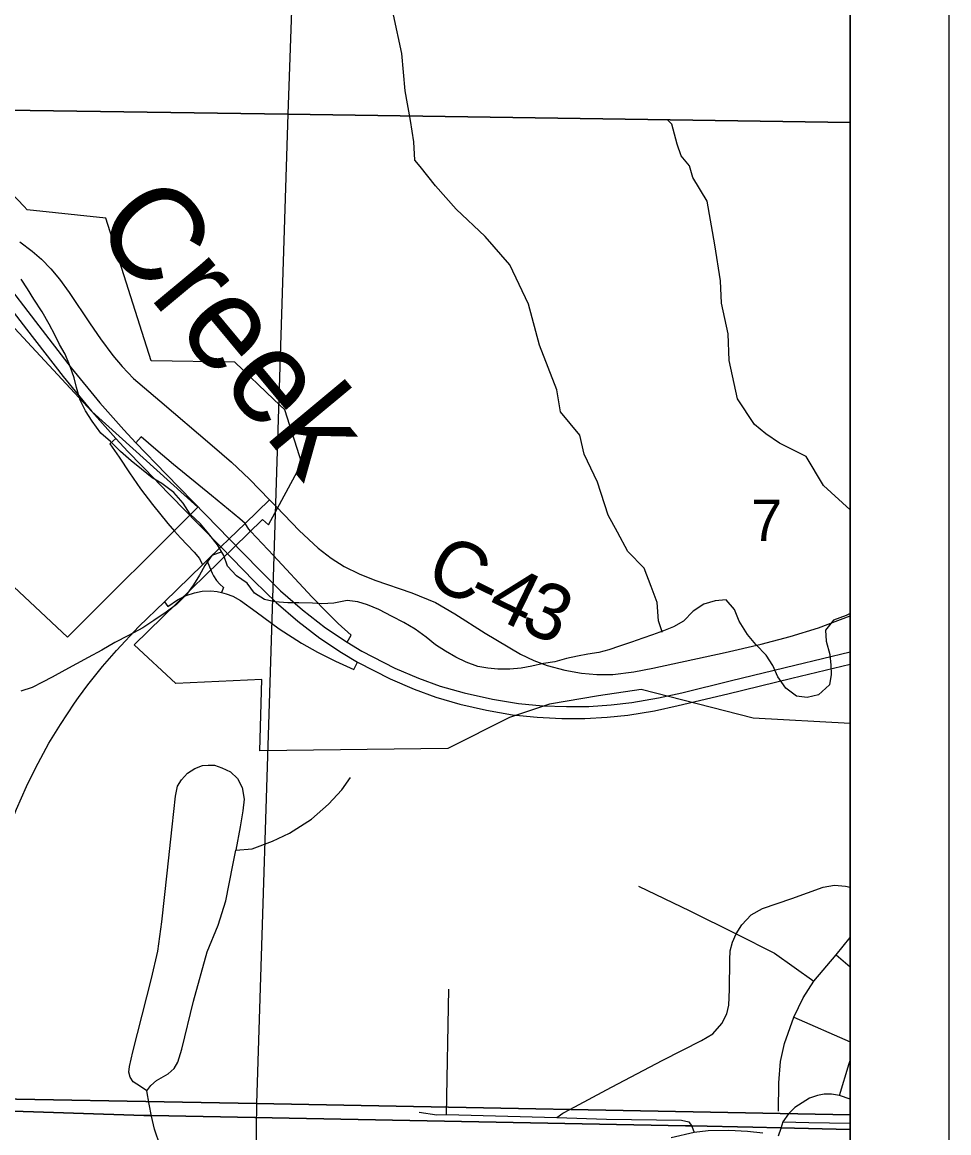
# Model space of a CAD drawing. Extents: x -19 to 40.8, y -1.8 to 26.1.
# Drawn here: x 8.061 to 9, y 15.876 to 17.001 of the extents above; entities that cross this region are included whole.
import ezdxf

# ---------------------------------------------------------------- set-up
doc = ezdxf.new("R2010")
doc.units = 0
for name, color, linetype in [('Default', 7, 'Continuous'), ('GM_X_Corporation', 7, 'Continuous'), ('GM_X_County_Road', 7, 'Continuous'), ('GM_X_County_Road_Text', 7, 'Continuous'), ('GM_X_Minor_River', 7, 'Continuous'), ('GM_X_Rail_Line', 7, 'Continuous'), ('GM_X_Rail_Line_Text', 7, 'Continuous'), ('GM_X_Section', 7, 'Continuous'), ('GM_X_Section_Text', 7, 'Continuous'), ('GM_X_State_Route', 7, 'Continuous'), ('GM_X_Township_Road', 7, 'Continuous'), ('RW_P_Text', 7, 'Continuous'), ('SH_Data', 7, 'Continuous')]:
    doc.layers.add(name, color=color, linetype=linetype)

msp = doc.modelspace()

# ---------------------------------------------------------------- linework, layer by layer
at = {"layer": 'Default'}
for p, q in [((8.0628, 16.814), (7.9759, 16.9049)), ((8.066, 16.8106), (8.0628, 16.814)), ((8.1458, 16.8022), (8.066, 16.8106)), ((8.1918, 16.6576), (8.1458, 16.8022)), ((8.0335, 16.7116), (8.1315, 16.6064)), ((8.2766, 16.6563), (8.1918, 16.6576)), ((8.3159, 16.6186), (8.2766, 16.6563)), ((8.327, 16.608), (8.3159, 16.6186)), ((8.1315, 16.6064), (8.2389, 16.5095)), ((8.3442, 16.5541), (8.327, 16.608)), ((8.3105, 16.4915), (8.3442, 16.5541)), ((8.2389, 16.5095), (8.107, 16.3778)), ((8.1743, 16.3699), (8.3044, 16.4969)), ((8.3044, 16.4969), (8.3105, 16.4915)), ((8.107, 16.3778), (8.0306, 16.4492)), ((8.2166, 16.3309), (8.1743, 16.3699)), ((8.3038, 16.335), (8.2166, 16.3309)), ((8.3017, 16.2626), (8.3038, 16.335)), ((8.6883, 16.3249), (8.645, 16.3183)), ((8.8018, 16.2956), (8.6883, 16.3249)), ((8.645, 16.3183), (8.5953, 16.3098)), ((8.5953, 16.3098), (8.5548, 16.2965)), ((8.5548, 16.2965), (8.4924, 16.2651)), ((8.9, 16.2904), (8.8018, 16.2956)), ((8.9, 14.2909), (8.9, 16.2904)), ((8.4924, 16.2651), (8.3017, 16.2626))]:
    msp.add_line(p, q, dxfattribs=at)
for points in [[(8.9, 16.8989), (8.9, 17.9188), (8.3666, 17.9389), (8.3301, 16.9076)], [(8.9, 15.8939), (8.9, 16.8989), (8.3301, 16.9076), (8.2983, 15.9055)], [(8.9, 14.8168), (8.9, 15.8939), (8.2983, 15.9055), (8.2842, 14.8321)]]:
    msp.add_lwpolyline(points, close=True, dxfattribs=at)
at = {"layer": 'GM_X_Corporation'}
for p, q in [((8.2868, 16.4928), (8.3116, 16.5169)), ((8.3116, 16.5169), (8.3186, 16.5097))]:
    msp.add_line(p, q, dxfattribs=at)
for points in [[(8.0586, 16.7781), (8.071, 16.7688), (8.0806, 16.7605), (8.0899, 16.7507), (8.0987, 16.7403), (8.1086, 16.7268), (8.13, 16.6951), (8.1403, 16.6798), (8.1528, 16.6632), (8.1623, 16.6518), (8.1739, 16.6399), (8.2004, 16.617), (8.2535, 16.5719), (8.2729, 16.555), (8.2913, 16.5377), (8.3116, 16.5169)], [(8.3186, 16.5097), (8.3418, 16.4858), (8.3609, 16.4678), (8.3741, 16.4578), (8.3873, 16.4493), (8.4023, 16.4419), (8.4183, 16.4355), (8.4557, 16.4228), (8.4799, 16.4127), (8.4993, 16.4013), (8.53, 16.3819), (8.5658, 16.3606), (8.5796, 16.3542), (8.5931, 16.3489), (8.6108, 16.3442), (8.6279, 16.3412), (8.6432, 16.3401), (8.6595, 16.3399), (8.6809, 16.3427), (8.7, 16.3465), (8.7732, 16.3623), (8.81, 16.3706), (8.8392, 16.3784), (8.8681, 16.3873), (8.9, 16.3995)], [(8.1181, 16.3165), (8.1276, 16.3294), (8.1422, 16.3479), (8.1564, 16.3644), (8.1793, 16.3885), (8.2051, 16.4136), (8.2436, 16.451), (8.248, 16.4553), (8.2622, 16.4691), (8.2707, 16.4773), (8.2868, 16.4928)], [(8.0146, 15.935), (8.0134, 15.9471), (8.0121, 15.9781), (8.0125, 16.0094), (8.0143, 16.0368), (8.0178, 16.0672), (8.0207, 16.0859), (8.0249, 16.1068), (8.0298, 16.1277), (8.0351, 16.1467), (8.0412, 16.1656), (8.0476, 16.1845), (8.0551, 16.2034), (8.0653, 16.2266), (8.0744, 16.2452), (8.0881, 16.2703), (8.0996, 16.2893), (8.114, 16.3108), (8.1181, 16.3165)], [(8.9, 15.9098), (8.8891, 15.9134), (8.8812, 15.9147), (8.8738, 15.9149), (8.8668, 15.9136), (8.8587, 15.9109), (8.8438, 15.9014), (8.8432, 15.9007)], [(8.8432, 15.9007), (8.8375, 15.895), (8.8319, 15.8868), (8.8298, 15.8801), (8.8272, 15.8722)]]:
    msp.add_lwpolyline(points, dxfattribs=at)
at = {"layer": 'GM_X_County_Road'}
for points in [[(8.2868, 16.4928), (8.2815, 16.4977), (8.2527, 16.5214), (8.2144, 16.5527), (8.1963, 16.5678), (8.1816, 16.5807), (8.1761, 16.5747)], [(8.1559, 16.5789), (8.1497, 16.5735), (8.1591, 16.56), (8.1696, 16.5443), (8.1809, 16.528), (8.1929, 16.512), (8.2085, 16.4928), (8.2154, 16.4852)], [(8.2927, 16.4848), (8.2905, 16.4872), (8.2868, 16.4928)], [(8.2154, 16.4852), (8.2215, 16.4785), (8.2353, 16.464), (8.2407, 16.4573), (8.2436, 16.451)], [(8.3904, 16.3726), (8.3944, 16.3799), (8.3811, 16.3915), (8.3703, 16.4023), (8.3546, 16.4187), (8.3157, 16.4604), (8.2927, 16.4848)], [(8.248, 16.4553), (8.2501, 16.4507), (8.2525, 16.4449)], [(8.2525, 16.4449), (8.2534, 16.4426), (8.2549, 16.4398), (8.2577, 16.4353), (8.2613, 16.4313), (8.2649, 16.428), (8.2628, 16.423)], [(8.2251, 16.4189), (8.227, 16.4198), (8.2354, 16.4227), (8.2432, 16.4242), (8.252, 16.4246), (8.2584, 16.424), (8.2628, 16.423), (8.2677, 16.4216), (8.2743, 16.4192), (8.2822, 16.4149), (8.2979, 16.4033), (8.3215, 16.3861), (8.3439, 16.3717), (8.3602, 16.3626), (8.3786, 16.3533), (8.3972, 16.3451), (8.4007, 16.3525)], [(8.2051, 16.4136), (8.2086, 16.4089), (8.2184, 16.4156), (8.2251, 16.4189)]]:
    msp.add_lwpolyline(points, dxfattribs=at)
at = {"layer": 'GM_X_Rail_Line'}
msp.add_lwpolyline([(8.8116, 15.8752), (8.7961, 15.877), (8.777, 15.8782), (8.7562, 15.8778), (8.7419, 15.8761), (8.7186, 15.8706)], dxfattribs=at)
at = {"layer": 'GM_X_Rail_Line_Text'}
for p, q in [((8.8859, 16.056), (8.9, 16.0438)), ((8.4911, 15.8944), (8.4932, 16.0213)), ((8.8431, 15.9928), (8.9, 15.9679))]:
    msp.add_line(p, q, dxfattribs=at)
for points in [[(8.1872, 15.9181), (8.1808, 15.9226), (8.1734, 15.9272), (8.1704, 15.9321), (8.169, 15.9371), (8.1696, 15.9428), (8.173, 15.9579), (8.1921, 16.0321), (8.1984, 16.0597), (8.2025, 16.0894), (8.2078, 16.1386), (8.2129, 16.1856), (8.2164, 16.2166), (8.2185, 16.2268), (8.2224, 16.2334), (8.2286, 16.2399), (8.2359, 16.2446), (8.2437, 16.2476), (8.2493, 16.2482), (8.2557, 16.248), (8.2634, 16.2455), (8.2722, 16.2413), (8.2793, 16.2347), (8.2838, 16.2256), (8.2859, 16.2136), (8.2847, 16.2017), (8.2819, 16.1856), (8.2774, 16.1621)], [(8.1872, 15.9181), (8.1912, 15.9237), (8.197, 15.9286), (8.2089, 15.9353), (8.2148, 15.9407), (8.2187, 15.9472), (8.2226, 15.9603), (8.2347, 16.0092), (8.2485, 16.0591), (8.2597, 16.0862), (8.2674, 16.1108), (8.2743, 16.1469), (8.2774, 16.1621), (8.2939, 16.1635), (8.3147, 16.1712), (8.3318, 16.1791), (8.3543, 16.1934), (8.3712, 16.2085), (8.385, 16.2231), (8.3938, 16.2355)], [(8.6027, 15.8913), (8.6088, 15.8955), (8.616, 15.8995), (8.6583, 15.9219), (8.7103, 15.9494), (8.7493, 15.9692), (8.7608, 15.9761), (8.77, 15.9863), (8.7752, 15.9964), (8.777, 16.0049), (8.7776, 16.0208), (8.7781, 16.051), (8.7785, 16.0601), (8.7807, 16.0687), (8.7845, 16.0774), (8.7903, 16.0865), (8.7996, 16.0964), (8.8112, 16.1029), (8.8408, 16.1132), (8.8728, 16.1246), (8.8842, 16.1265), (8.8954, 16.1256), (8.9, 16.1246)], [(8.6856, 16.1255), (8.7374, 16.1004), (8.7845, 16.0774), (8.8235, 16.0577), (8.8631, 16.0292)], [(8.8274, 15.8975), (8.8279, 15.9264), (8.8295, 15.948), (8.8335, 15.9662), (8.8431, 15.9928), (8.8524, 16.0124), (8.8631, 16.0292), (8.8859, 16.056), (8.9, 16.0737)], [(8.8891, 15.9134), (8.899, 15.9459), (8.9, 15.9489)], [(8.3504, 15.7054), (8.3429, 15.7215), (8.3351, 15.7346), (8.3259, 15.7469), (8.3131, 15.7589), (8.3012, 15.7689), (8.2884, 15.78), (8.262, 15.8029), (8.2354, 15.8263), (8.2097, 15.8491), (8.2007, 15.8627), (8.1951, 15.8793), (8.1921, 15.8926), (8.1895, 15.9046), (8.1872, 15.9181)], [(8.4632, 15.8965), (8.4812, 15.8939), (8.4911, 15.8944), (8.6027, 15.8913), (8.6532, 15.8895), (8.7291, 15.8884), (8.7364, 15.887), (8.7397, 15.8825), (8.7419, 15.8761)], [(8.8319, 15.8868), (8.8581, 15.8861), (8.9, 15.8856)]]:
    msp.add_lwpolyline(points, dxfattribs=at)
at = {"layer": 'GM_X_Section'}
for points in [[(8.709, 16.3834), (8.7094, 16.3832), (8.7059, 16.3942), (8.7044, 16.4128), (8.6984, 16.429), (8.6913, 16.4475), (8.6747, 16.4644), (8.6642, 16.484), (8.6548, 16.5013), (8.644, 16.5346), (8.6306, 16.5632), (8.6261, 16.5825), (8.6064, 16.6061), (8.6026, 16.6281), (8.5852, 16.6734), (8.5739, 16.7151), (8.555, 16.7547), (8.5303, 16.7835), (8.5007, 16.8112), (8.4799, 16.8348), (8.4644, 16.8543), (8.459, 16.861), (8.4579, 16.8796), (8.4545, 16.9009), (8.4491, 16.9312), (8.4457, 16.9688), (8.4371, 17.0081)], [(8.9, 16.5067), (8.8731, 16.5315), (8.8556, 16.5608), (8.8285, 16.5741), (8.8147, 16.5837), (8.8032, 16.593), (8.7858, 16.619), (8.7775, 16.658), (8.7763, 16.6849), (8.7697, 16.716), (8.7685, 16.7388), (8.7629, 16.7752), (8.755, 16.8195), (8.7406, 16.8432), (8.7373, 16.8553), (8.7288, 16.8654), (8.7248, 16.8772), (8.7192, 16.8972), (8.7149, 16.9017)], [(8.8458, 16.318), (8.8349, 16.326), (8.8269, 16.3376), (8.8216, 16.3492), (8.8148, 16.3596), (8.8046, 16.3703), (8.7959, 16.3803), (8.7875, 16.3941), (8.7829, 16.4058), (8.7743, 16.4154), (8.7633, 16.4147), (8.7516, 16.4113), (8.7408, 16.4041), (8.7312, 16.3939), (8.7211, 16.3883), (8.711, 16.3841), (8.6997, 16.38), (8.6899, 16.3766), (8.6783, 16.3728), (8.6662, 16.3687), (8.6553, 16.3649), (8.6455, 16.3623), (8.6342, 16.3604), (8.6236, 16.3586), (8.6126, 16.356), (8.6006, 16.3529), (8.5892, 16.3511), (8.5775, 16.3484), (8.5666, 16.3462), (8.5552, 16.3454), (8.543, 16.3454), (8.5327, 16.3463), (8.5228, 16.3479), (8.5109, 16.3524), (8.5005, 16.3574), (8.49, 16.3636), (8.4799, 16.3701), (8.4702, 16.3778), (8.4593, 16.3858), (8.4476, 16.3927), (8.436, 16.3988), (8.4225, 16.4056), (8.411, 16.4105), (8.401, 16.4137), (8.3903, 16.4148), (8.3767, 16.4121), (8.3646, 16.4114), (8.355, 16.4122), (8.3413, 16.4126), (8.3303, 16.4126), (8.317, 16.4137), (8.3066, 16.416), (8.2965, 16.4222), (8.289, 16.4326), (8.2781, 16.4399), (8.2691, 16.4495), (8.2653, 16.4604), (8.2589, 16.4712), (8.2498, 16.4827), (8.2415, 16.4927), (8.2313, 16.5023), (8.2241, 16.5135), (8.2146, 16.5242), (8.2026, 16.5334), (8.1925, 16.5391), (8.182, 16.5479), (8.1714, 16.5563), (8.1605, 16.5659), (8.1503, 16.5758), (8.1405, 16.5843), (8.1318, 16.5966), (8.125, 16.607), (8.1197, 16.6179), (8.1159, 16.6307), (8.1137, 16.6405), (8.1095, 16.6518), (8.1046, 16.6645), (8.0989, 16.6743), (8.0941, 16.684), (8.0884, 16.6948), (8.0812, 16.7072), (8.0728, 16.7202), (8.0664, 16.7307), (8.06, 16.7404)], [(8.2631, 16.4641), (8.2531, 16.4604), (8.2462, 16.4503), (8.2408, 16.4406), (8.2347, 16.4306), (8.2274, 16.4208), (8.2174, 16.411), (8.2067, 16.4031), (8.1944, 16.3947), (8.1832, 16.3871), (8.1686, 16.3795), (8.1548, 16.3722), (8.1417, 16.3646), (8.1279, 16.3573), (8.104, 16.3444), (8.0913, 16.3372), (8.0815, 16.3323), (8.0711, 16.3266), (8.0594, 16.3229)], [(8.9, 16.4017), (8.896, 16.3998), (8.8833, 16.3948), (8.8752, 16.3847), (8.8756, 16.3737), (8.8794, 16.3601), (8.8805, 16.3495), (8.8808, 16.34), (8.8792, 16.3293), (8.8681, 16.3195), (8.8564, 16.3168), (8.8458, 16.318)]]:
    msp.add_lwpolyline(points, dxfattribs=at)
at = {"layer": 'GM_X_State_Route'}
for points in [[(6.9993, 15.9207), (7.1288, 15.9169), (7.6101, 15.9059), (8.0135, 15.8966), (8.0191, 15.8965), (8.0312, 15.8982), (8.1843, 15.8933), (8.1919, 15.8932), (8.7332, 15.8828), (8.7397, 15.8827), (8.8013, 15.8813), (8.8296, 15.8807), (8.9, 15.8791), (8.9, 20.9)], [(4.3215, 14.1), (8.9, 14.1), (8.9, 15.8791), (8.8296, 15.8807), (8.8013, 15.8813), (8.7397, 15.8827), (8.7332, 15.8828), (8.1919, 15.8932), (8.1843, 15.8933), (8.0312, 15.8982), (8.0191, 15.8965), (8.0135, 15.8966), (7.6101, 15.9059), (7.1288, 15.9169), (6.9993, 15.9207)]]:
    msp.add_lwpolyline(points, dxfattribs=at)
at = {"layer": 'GM_X_Township_Road'}
for points in [[(8.0423, 16.7392), (8.0744, 16.6976), (8.1106, 16.6505), (8.1396, 16.6152), (8.1639, 16.5877), (8.1761, 16.5747), (8.207, 16.5427), (8.2473, 16.5012), (8.2707, 16.4773), (8.3015, 16.4458), (8.3228, 16.4248), (8.3449, 16.4055), (8.3684, 16.3872), (8.3904, 16.3726), (8.4051, 16.3636), (8.4385, 16.3464), (8.4627, 16.3363), (8.4847, 16.3282), (8.509, 16.3214), (8.5375, 16.315), (8.5639, 16.3107), (8.5886, 16.3083), (8.6124, 16.3074), (8.6353, 16.3076), (8.6579, 16.3092), (8.6789, 16.3117), (8.7059, 16.3163), (8.7295, 16.3214), (8.7797, 16.3338), (8.844, 16.3495), (8.9, 16.363)], [(8.0313, 16.7337), (8.0654, 16.6898), (8.1026, 16.6417), (8.1316, 16.6064), (8.1559, 16.5789)], [(8.1559, 16.5789), (8.1681, 16.5659), (8.1965, 16.5366)], [(8.1965, 16.5366), (8.1985, 16.5345), (8.2388, 16.4929), (8.2622, 16.4691), (8.2961, 16.4344), (8.3183, 16.4129), (8.3402, 16.3939), (8.3627, 16.3768), (8.3847, 16.3622), (8.4007, 16.3525), (8.434, 16.3354), (8.4583, 16.3252), (8.4802, 16.3171), (8.5046, 16.31), (8.5315, 16.3037), (8.5578, 16.2991), (8.583, 16.2967), (8.5889, 16.2964)], [(8.5889, 16.2964), (8.6078, 16.2953), (8.6311, 16.2954), (8.6538, 16.2966), (8.6746, 16.2989), (8.7017, 16.3032), (8.7257, 16.3085), (8.7762, 16.3203), (8.8408, 16.3361), (8.9, 16.3505)]]:
    msp.add_lwpolyline(points, dxfattribs=at)
at = {"layer": 'RW_P_Text'}
for points in [[(7.3559, 17.9489), (8.3666, 17.9389), (8.3301, 16.9076), (7.309, 16.9219)], [(8.3301, 16.9076), (8.2983, 15.9055), (7.2877, 15.9238), (7.309, 16.9219)], [(7.2877, 15.9238), (8.2983, 15.9055), (8.2842, 14.8321), (7.2668, 14.8526)]]:
    msp.add_lwpolyline(points, close=True, dxfattribs=at)
at = {"layer": 'SH_Data'}
for p, q in [((9, 21), (9, 14)), ((8.9, 20.9), (8.9, 14.1))]:
    msp.add_line(p, q, dxfattribs=at)

# ---------------------------------------------------------------- texts
at = {"layer": 'GM_X_County_Road_Text'}
for s, rotation, p in [('C', 333.8324, (8.467, 16.4332)), ('4', 333.9917, (8.5295, 16.4025)), ('-', 333.8615, (8.5086, 16.4127)), ('3', 337.2119, (8.5639, 16.3858))]:
    msp.add_text(s, height=0.0568, rotation=rotation, dxfattribs=at).set_placement(p)
at = {"layer": 'GM_X_Minor_River'}
msp.add_text('Creek', height=0.09471, rotation=309.7532, dxfattribs=at).set_placement((8.1303, 16.793))
at = {"layer": 'GM_X_Section_Text'}
msp.add_text('7', height=0.0419, rotation=0, dxfattribs=at).set_placement((8.7998, 16.4752))

doc.saveas('drawing.dxf')
